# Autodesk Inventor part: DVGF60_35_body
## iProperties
Created: 2010-04
Part Number: DVGF60_35_body
Document SubType Name: Modeling
Designer: TB
Mass: 715.027 g
Surface Area: 1340.92 cm^2
Volume: 715.027 cm^3
Density: 1 g/cm^3
Author: TB
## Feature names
1. Kropp [Revolution]
2. Chamfer
3. Extrusion2
4. Hole1
5. Revolution2
6. Hole2
7. Fillet1
8. Extrusion3
9. Hole3
